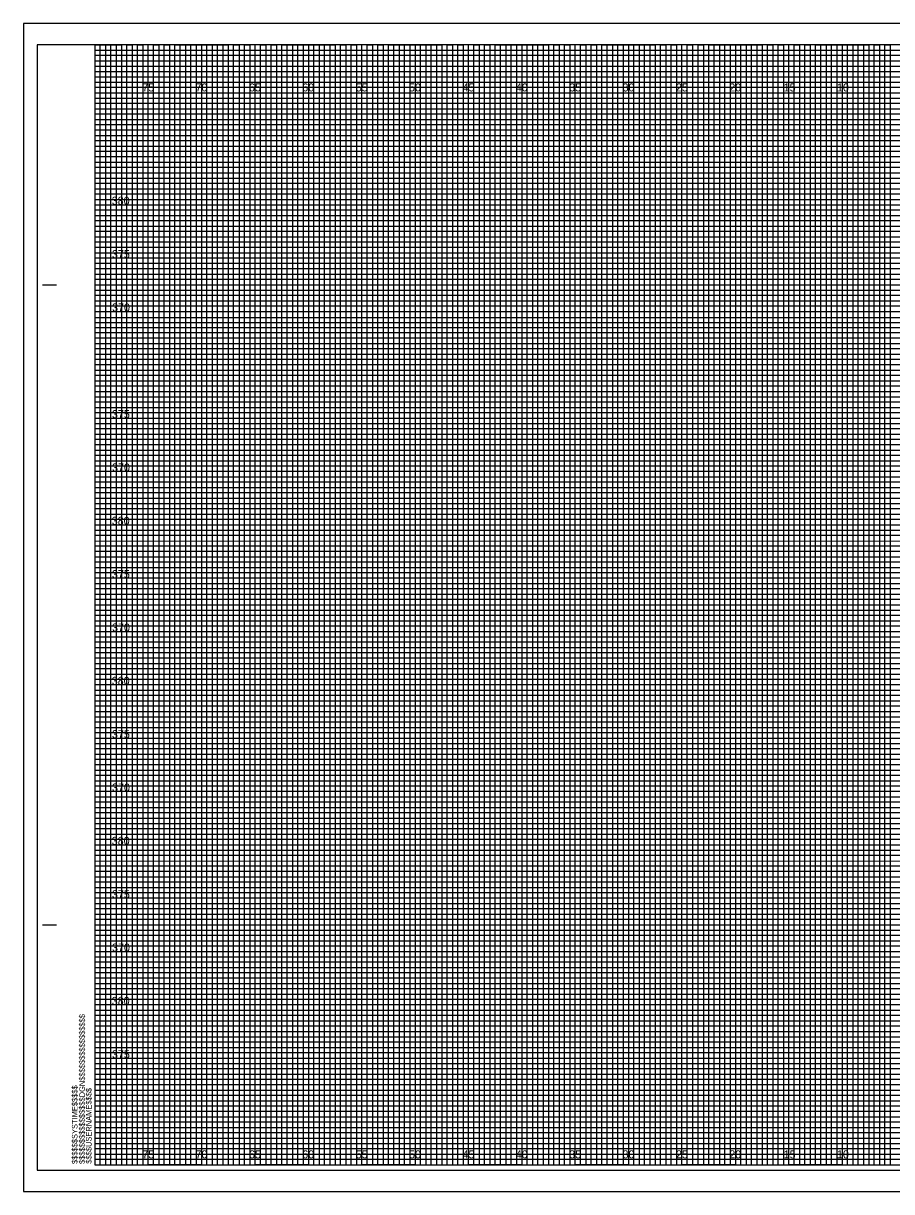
# Model space of a CAD drawing. Extents: x -7 to 162, y -2 to 107.
# Drawn here: x -6.7 to 74.6, y -2.5 to 107 of the extents above; entities that cross this region are included whole.
import ezdxf

# ---------------------------------------------------------------- set-up
doc = ezdxf.new("R2010")
doc.units = 0
for name, color, linetype in [('Exist Cross Section Cell', 7, 'Continuous'), ('Prop CMT Pvmt Course 1', 7, 'Continuous'), ('Prop CMT Pvmt Course 3', 7, 'Continuous'), ('Prop CMT Shld Paved Course 1', 7, 'Continuous'), ('Prop CMT Shld Paved Course 2', 7, 'Continuous'), ('Prop CMT Shld Paved Course 3', 7, 'Continuous'), ('Prop CMT Slope Grass', 7, 'Continuous'), ('Prop CMT Subgrade Earthwork', 7, 'Continuous'), ('Scratch_Level_3', 7, 'Continuous')]:
    doc.layers.add(name, color=color, linetype=linetype)

msp = doc.modelspace()

# ---------------------------------------------------------------- linework, layer by layer
at = {"layer": 'Prop CMT Pvmt Course 3'}
msp.add_lwpolyline([(-6.7, -2.5), (161.65, -2.5), (161.65, 107), (-6.7, 107)], close=True, dxfattribs=at)
at = {"layer": 'Prop CMT Shld Paved Course 1'}
for p, q in [((0, 104.5), (110.95, 104.5)), ((110.95, 103.99), (0, 103.99)), ((0, 103.99), (0, 103.5)), ((0, 103.5), (110.95, 103.5)), ((110.95, 102.95), (0, 102.95)), ((0, 102.95), (0, 102)), ((0, 102), (160, 102))]:
    msp.add_line(p, q, dxfattribs=at)
for points in [[(0, 101.5), (135, 101.5), (160, 101.5)], [(160, 101), (0, 101)], [(0, 100.5), (160, 100.5)], [(160, 99.5), (0, 99.5)], [(0, 99), (160, 99)], [(160, 98.5), (0, 98.49)], [(0, 98), (160, 98)], [(160, 97), (0, 97)], [(0, 96.5), (160, 96.5), (160, 96), (0, 96)], [(0, 95.5), (160, 95.5), (160, 94.5), (0, 94.5)], [(0, 94), (160, 94), (160, 93.5), (0, 93.5)], [(0, 93), (160, 93), (160, 92), (0, 92)], [(0, 91.5), (160, 91.5), (160, 91), (0, 91)], [(0, 90.5), (160, 90.5), (160, 89.5), (0, 89.5)], [(0, 89), (160, 89), (160, 88.5), (0, 88.5)], [(0, 88), (160, 88), (160, 86.97), (160, 86.5), (160, 86), (0, 86)], [(0, 87), (160, 87), (160, 86.5), (0, 86.5)], [(0, 85.5), (160, 85.5), (160, 84.5), (0, 84.51)], [(0, 84.51), (160, 84.5), (160, 84), (0, 84)], [(0, 83.5), (160, 83.5), (160, 83), (0, 83)], [(0, 82), (160, 82), (160, 81.5), (0, 81.5)], [(0, 81), (160, 81), (160, 80.5), (0, 80.5)], [(-0.04, 79.44), (160, 79.44), (160, 78.94), (-0.04, 78.94)], [(0, 78.5), (160, 78.5), (160, 78), (0, 78)], [(0, 77), (160, 77), (160, 76.5), (0, 76.5)], [(0, 76), (160, 76), (160, 75.5), (0, 75.5)], [(0, 74.5), (160, 74.5), (160, 74), (0, 74)], [(0, 73.5), (160, 73.5), (160, 73), (0, 73)], [(0, 72), (160, 72), (160, 71.5), (0, 71.5)], [(0, 71), (160, 71), (160, 70.5), (0, 70.5)], [(0, 69.5), (160, 69.5), (159.99, 68.99), (0, 69)], [(0, 68.5), (160, 68.5), (160, 68), (0, 68)], [(0, 67), (160, 67), (160, 66.5), (0, 66.5)], [(0, 66), (160, 66), (160, 65.5), (0, 65.5)], [(0, 64.5), (160, 64.5), (160, 64), (0, 64)], [(0, 63.5), (160, 63.5), (160, 63), (0, 63)], [(0, 62), (160, 62), (160, 61.5), (0, 61.5)], [(0, 61), (160, 61), (160, 60.5), (0, 60.5)], [(0, 59.5), (160, 59.5), (160, 59), (0, 59)], [(0, 58.5), (160.03, 58.45), (160, 58), (0, 58)], [(0, 57), (160, 57), (160, 56.5), (0, 56.5)], [(0, 56), (160, 56), (160, 55.5), (0, 55.5)], [(0, 54.5), (160, 54.5), (160, 54), (0, 54)], [(0, 53.5), (160, 53.5), (160, 53), (0, 53)], [(0, 52), (160, 52), (160, 51.5), (0, 51.5)], [(0, 51), (160, 51), (160, 50.5), (0, 50.5)], [(0, 49.5), (160, 49.5), (160, 49), (0, 49)], [(0, 48.5), (160, 48.5), (160, 48), (0, 48)], [(0, 47), (160, 47), (160, 46.5), (0, 46.5)], [(0, 46), (160, 46), (160, 45.5), (0, 45.5)], [(0, 44.5), (160, 44.5), (160, 44), (0, 44)], [(0, 43.5), (160, 43.5), (160, 43), (0, 43)], [(0, 42), (160, 42), (160, 41.5), (0, 41.5)], [(0, 41), (160, 41), (160, 40.5), (0, 40.5)], [(0, 39.5), (160, 39.5), (159.99, 38.99), (0, 39)], [(0, 38.5), (160, 38.5), (160, 38), (0, 38)], [(0, 37), (160, 37), (160, 36.5), (0, 36.5)], [(0, 36), (160, 36), (160, 35.5), (0, 35.5)], [(0, 34.5), (160, 34.5), (160, 34), (0, 34)], [(0, 33.5), (160, 33.5), (160, 33), (0, 33)], [(0, 32), (160, 32), (160, 31.5), (0, 31.5)], [(0, 31), (160, 31), (160, 30.5), (0, 30.5)], [(0, 29.5), (160, 29.5), (160, 29), (0, 29)], [(0, 28.5), (160.03, 28.46), (160, 28), (0, 28)], [(0, 27), (160, 27), (160, 26.5), (0, 26.5)], [(0, 26), (160, 26), (160, 25.5), (0, 25.5)], [(0, 24.5), (160, 24.5), (160, 24), (0, 24)], [(0, 23.5), (160, 23.5), (160, 23), (0, 23)], [(0, 22), (160, 22), (160, 21.5), (0, 21.5)], [(0, 21), (160, 21), (160, 20.5), (0, 20.5)], [(0, 19.5), (160, 19.5), (160, 19), (0, 19)], [(0, 18.5), (160, 18.5), (160, 18), (0, 18)], [(0, 17), (160, 17), (160, 16.5), (0, 16.5)], [(0, 16), (160, 16), (160, 15.5), (0, 15.5)], [(0, 14.5), (160, 14.5), (160, 14), (0, 14)], [(0, 13.5), (160, 13.5), (160, 13), (0, 13)], [(0, 12), (160, 12), (160, 11.5), (0, 11.5)], [(0, 11), (160, 11), (160, 10.5), (0, 10.5)], [(0, 9.5), (160, 9.5), (160, 9), (0, 9)], [(0, 8.5), (160, 8.5), (160, 8), (0, 8)], [(0, 7), (160, 7), (160, 6.5), (0, 6.5)], [(0, 6), (160, 6), (160, 5.5), (0, 5.5)], [(0, 4.5), (160, 4.5), (160, 4), (0, 4)], [(0, 3.5), (160, 3.5), (160, 3), (0, 3)], [(0, 2), (160, 2), (160, 1.5), (0, 1.5)], [(0, 1), (160, 1), (160, 0.5), (0, 0.5)]]:
    msp.add_lwpolyline(points, dxfattribs=at)
at = {"layer": 'Prop CMT Shld Paved Course 2'}
for p, q in [((-4.9, 82.5), (-3.65, 82.5)), ((-4.85, 82.5), (-3.6, 82.5)), ((-4.9, 22.5), (-3.65, 22.5)), ((-4.85, 22.5), (-3.6, 22.5)), ((0, 0), (0, 0)), ((0, 0), (0, 0)), ((0, 0), (0, 0)), ((0, 0), (0, 0)), ((0, 0), (0, 0)), ((0, 0), (0, 0)), ((0, 0), (0, 0))]:
    msp.add_line(p, q, dxfattribs=at)
msp.add_lwpolyline([(160, 105), (0, 105), (0, 0), (160, 0)], close=True, dxfattribs=at)
at = {"layer": 'Prop CMT Shld Paved Course 3'}
for points in [[(0, 0), (0.5, 0), (0.5, 105), (1, 105), (1, 0)], [(1, 0), (1.5, 0), (1.5, 105), (2, 105), (2, 0)], [(2.5, 0), (3, 0), (3, 105), (3.5, 105), (3.5, 0)], [(3.5, 0), (4, 0), (4, 105), (4.5, 105), (4.5, 0)], [(5, 0), (5.5, 0), (5.5, 105), (6, 105), (6, 0)], [(6, 0), (6.5, 0), (6.5, 105), (7, 105), (7, 0)], [(7.5, 0), (8, 0), (8, 105), (8.5, 105), (8.5, 0)], [(8.5, 0), (9, 0), (9, 105), (9.5, 105), (9.5, 0)], [(10, 0), (10.5, 0), (10.5, 105), (11, 105), (11, 0)], [(11, 0), (11.5, 0), (11.5, 105), (12, 105), (12, 0)], [(12.5, 0), (13, 0), (13, 105), (13.5, 105), (13.5, 0)], [(13.5, 0), (14, 0), (14, 105), (14.5, 105), (14.5, 0)], [(15, 0), (15.5, 0), (15.5, 105), (16, 105), (16, 0)], [(16, 0), (16.5, 0), (16.5, 105), (17, 105), (17, 0)], [(17.5, 0), (18, 0), (18, 105), (18.5, 105), (18.5, 0)], [(18.5, 0), (19, 0), (19, 105), (19.5, 105), (19.5, 0)], [(20, 0), (20.5, 0), (20.5, 105), (21, 105), (21, 0)], [(21, 0), (21.5, 0), (21.5, 105), (22, 105), (22, 0)], [(22.5, 0), (23, 0), (23, 105), (23.5, 105), (23.5, 0)], [(23.5, 0), (24, 0), (24, 105), (24.5, 105), (24.5, 0)], [(25, 0), (25.5, 0), (25.5, 105), (26, 105), (26, 0)], [(26, 0), (26.5, 0), (26.5, 105), (27, 105), (27, 0)], [(27.5, 0), (28, 0), (28, 105), (28.5, 105), (28.5, 0)], [(28.5, 0), (29, 0), (29, 105), (29.5, 105), (29.5, 0)], [(30, 0), (30.5, 0), (30.5, 105), (31, 105), (31, 0)], [(31, 0), (31.5, 0), (31.5, 105), (32, 105), (32, 0)], [(32.5, 0), (33, 0), (33, 105), (33.5, 105), (33.5, 0)], [(33.5, 0), (34, 0), (34, 105), (34.5, 105), (34.5, 0)], [(35, 0), (35.5, 0), (35.5, 105), (36, 105), (36, 0)], [(36, 0), (36.5, 0), (36.5, 105), (37, 105), (37, 0)], [(37.5, 0), (38, 0), (38, 105), (38.5, 105), (38.5, 0)], [(38.5, 0), (39, 0), (39, 105), (39.5, 105), (39.5, 0)], [(40, 0), (40.5, 0), (40.5, 105), (41, 105), (41, 0)], [(41, 0), (41.5, 0), (41.5, 105), (42, 105), (42, 0)], [(42.5, 0), (43, 0), (43, 105), (43.5, 105), (43.5, 0)], [(43.5, 0), (44, 0), (44, 105), (44.5, 105), (44.5, 0)], [(45, 0), (45.5, 0), (45.5, 105), (46, 105), (46, 0)], [(46, 0), (46.5, 0), (46.5, 105), (47, 105), (47, 0)], [(47.5, 0), (48, 0), (48, 105), (48.5, 105), (48.5, 0)], [(48.5, 0), (49, 0), (49, 105), (49.5, 105), (49.5, 0)], [(50, 0), (50.5, 0), (50.5, 105), (51, 105), (51, 0)], [(51, 0), (51.5, 0), (51.5, 105), (52, 105), (52, 0)], [(52.5, 0), (53, 0), (53, 105), (53.5, 105), (53.5, 0)], [(53.5, 0), (54, 0), (54, 105), (54.5, 105), (54.5, 0)], [(55, 0), (55.5, 0), (55.5, 105), (56, 105), (56, 0)], [(56, 0), (56.5, 0), (56.5, 105), (57, 105), (57, 0)], [(57.5, 0), (58, 0), (58, 105), (58.5, 105), (58.5, 0)], [(58.5, 0), (59, 0), (59, 105), (59.5, 105), (59.5, 0)], [(60, 0), (60.5, 0), (60.5, 105), (61, 105), (61, 0)], [(61, 0), (61.5, 0), (61.5, 105), (62, 105), (62, 0)], [(62.5, 0), (63, 0), (63, 105), (63.5, 105), (63.5, 0)], [(63.5, 0), (64, 0), (64, 105), (64.5, 105), (64.5, 0)], [(65, 0), (65.5, 0), (65.5, 105), (66, 105), (66, 0)], [(66, 0), (66.5, 0), (66.5, 105), (67, 105), (67, 0)], [(67.5, 0), (68, 0), (68, 105), (68.5, 105), (68.5, 0)], [(68.5, 0), (69, 0), (69, 105), (69.5, 105), (69.5, 0)], [(70, 0), (70.5, 0), (70.5, 105), (71, 105), (71, 0)], [(71, 0), (71.5, 0), (71.5, 105), (72, 105), (72, 0)], [(72.5, 0), (73, 0), (73, 105), (73.5, 105), (73.5, 0)], [(73.5, 0), (74, 0), (74, 105), (74.5, 105), (74.5, 0)]]:
    msp.add_lwpolyline(points, dxfattribs=at)
at = {"layer": 'Prop CMT Slope Grass'}
for points in [[(0, 105), (2.5, 105), (2.5, 0), (7.5, 0), (7.5, 105), (12.5, 105), (12.5, 0), (17.5, 0), (17.5, 105), (22.5, 105), (22.5, 0), (27.5, 0), (27.5, 105), (32.5, 105), (32.5, 0), (37.5, 0), (37.5, 105), (42.5, 105), (42.5, 0), (47.5, 0), (47.5, 105), (52.5, 105), (52.5, 0), (57.5, 0), (57.5, 105), (62.5, 105), (62.5, 0), (67.5, 0), (67.5, 105), (72.5, 105), (72.5, 0), (77.5, 0)], [(0, 102.5), (137.5, 102.5)], [(0, 92.5), (160, 92.5), (160, 102.5)], [(160, 97.5), (0, 97.5)], [(0, 82.5), (160, 82.5), (160, 87.5), (0, 87.5)], [(0, 72.5), (160, 72.5), (160, 77.5), (0, 77.5)], [(0, 62.5), (160, 62.5), (160, 67.5), (0, 67.5)], [(0, 52.5), (160, 52.5), (160, 57.5), (0, 57.5)], [(0, 42.5), (160, 42.5), (160, 47.5), (0, 47.5)], [(0, 32.5), (160, 32.5), (160, 37.5), (0, 37.5)], [(0, 22.5), (160, 22.5), (160, 27.5), (0, 27.5)], [(0, 12.5), (160, 12.5), (160, 17.5), (0, 17.5)], [(0, 2.5), (160, 2.5), (160, 7.5), (0, 7.5)]]:
    msp.add_lwpolyline(points, dxfattribs=at)
at = {"layer": 'Prop CMT Subgrade Earthwork'}
msp.add_lwpolyline([(-5.4, -0.5), (161.2, -0.5), (161.2, 105), (-5.4, 105)], close=True, dxfattribs=at)
at = {"layer": 'Scratch_Level_3'}
for p, q in [((5, 105), (0, 105)), ((5, 0), (5, 105)), ((15, 105), (10, 105)), ((10, 105), (10, 0)), ((15, 0), (15, 105)), ((25, 105), (20, 105)), ((20, 105), (20, 0)), ((25, 0), (25, 105)), ((35, 105), (30, 105)), ((30, 105), (30, 0)), ((35, 0), (35, 105)), ((45, 105), (40, 105)), ((40, 105), (40, 0)), ((45, 0), (45, 105)), ((55, 105), (50, 105)), ((50, 105), (50, 0)), ((55, 0), (55, 105)), ((65, 105), (60, 105)), ((60, 105), (60, 0)), ((65, 0), (65, 105)), ((75, 105), (70, 105)), ((70, 105), (70, 0)), ((10, 0), (5, 0)), ((20, 0), (15, 0)), ((30, 0), (25, 0)), ((40, 0), (35, 0)), ((60, 0), (55, 0)), ((70, 0), (65, 0)), ((50, 0), (45, 0))]:
    msp.add_line(p, q, dxfattribs=at)
for points in [[(160, 102.5), (160, 95), (0, 95)], [(0, 100), (160, 100)], [(0, 90), (160, 90), (160, 85), (0, 85)], [(0, 80), (160, 80), (160, 75), (0, 75)], [(0, 70), (160, 70), (160, 65), (0, 65)], [(0, 60), (160, 60), (160, 55), (0, 55)], [(0, 50), (160, 50), (160, 45), (0, 45)], [(0, 40), (160, 40), (160, 35), (0, 35)], [(0, 30), (160, 30), (160, 25), (0, 25)], [(0, 20), (160, 20), (160, 15), (0, 15)], [(0, 10), (160, 10), (160, 5), (0, 5)]]:
    msp.add_lwpolyline(points, dxfattribs=at)

# ---------------------------------------------------------------- texts
at = {"layer": 'Exist Cross Section Cell'}
for s, p in [('75', (4.44, 100.62)), ('70', (9.43, 100.62)), ('65', (14.44, 100.62)), ('60', (19.43, 100.62)), ('55', (24.44, 100.62)), ('50', (29.43, 100.62)), ('45', (34.44, 100.62)), ('40', (39.43, 100.62)), ('35', (44.44, 100.62)), ('30', (49.43, 100.62)), ('25', (54.44, 100.62)), ('20', (59.43, 100.62)), ('15', (64.53, 100.62)), ('10', (69.52, 100.62)), ('75', (4.44, 0.62)), ('70', (9.43, 0.62)), ('65', (14.44, 0.62)), ('60', (19.43, 0.62)), ('55', (24.44, 0.62)), ('50', (29.43, 0.62)), ('45', (34.44, 0.62)), ('40', (39.43, 0.62)), ('35', (44.44, 0.62)), ('30', (49.43, 0.62)), ('25', (54.44, 0.62)), ('20', (59.43, 0.62)), ('15', (64.53, 0.62)), ('10', (69.52, 0.62))]:
    msp.add_text(s, height=0.75, dxfattribs=at).set_placement(p)
at = {"layer": 'Prop CMT Pvmt Course 1'}
for s, p in [('380', (1.58, 90)), ('375', (1.6, 85)), ('370', (1.61, 80)), ('375', (1.6, 70)), ('370', (1.61, 65)), ('380', (1.58, 60)), ('375', (1.6, 55)), ('370', (1.61, 50)), ('380', (1.58, 45)), ('375', (1.6, 40)), ('370', (1.61, 35)), ('380', (1.58, 30)), ('375', (1.6, 25)), ('370', (1.61, 20)), ('380', (1.58, 15)), ('375', (1.6, 10))]:
    msp.add_text(s, height=0.75, dxfattribs=at).set_placement(p)
at = {"layer": 'Prop CMT Shld Paved Course 2'}
for s, p in [('$$$$$$$$$$$$$$$$DGN$$$$$$$$$$$$$$$$', (-0.94, 0.09)), ('$$$$$$SYSTIME$$$$$', (-1.63, 0.09)), ('$$$$USERNAME$$$$', (-0.31, 0.12))]:
    msp.add_text(s, height=0.525, rotation=90, dxfattribs=at).set_placement(p)

doc.saveas('drawing.dxf')
